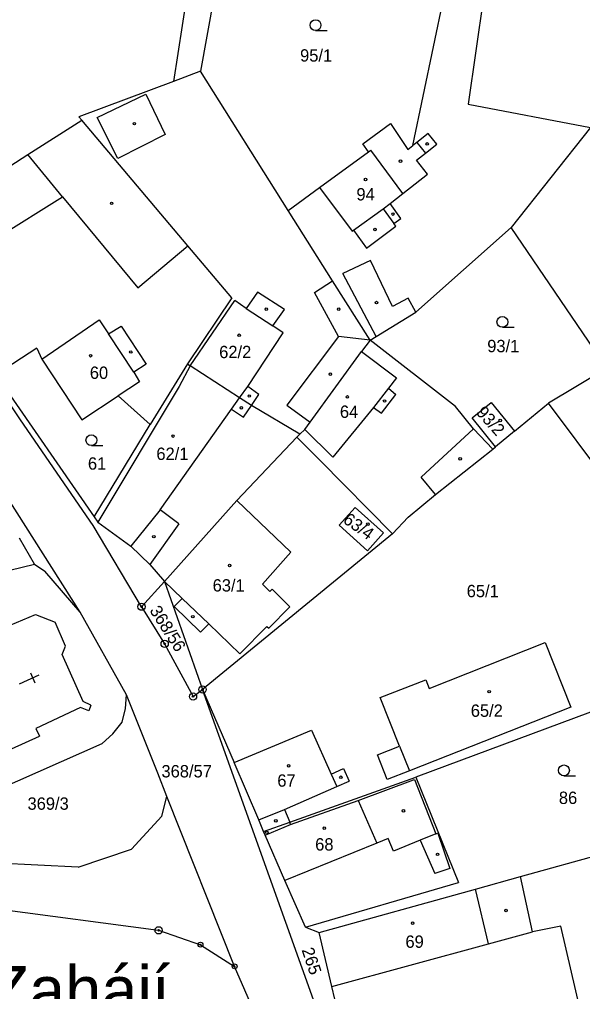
# Model space of a CAD drawing. Extents: x -762263 to -760336, y -1154405 to -1152076.
# Drawn here: x -761616.2 to -761538.5, y -1152485.2 to -1152351.2 of the extents above; entities that cross this region are included whole.
import ezdxf

# ---------------------------------------------------------------- set-up
doc = ezdxf.new("R2010")
doc.units = 0
for name, color, linetype in [('Vrstva 1', 7, 'Continuous'), ('Vrstva 15', 7, 'Continuous'), ('Vrstva 18', 7, 'Continuous'), ('Vrstva 19', 7, 'Continuous'), ('Vrstva 24', 7, 'Continuous'), ('Vrstva 25', 7, 'Continuous'), ('Vrstva 4', 7, 'Continuous'), ('Vrstva 6', 7, 'Continuous')]:
    doc.layers.add(name, color=color, linetype=linetype)

msp = doc.modelspace()

# ---------------------------------------------------------------- linework, layer by layer
at = {"layer": 'Vrstva 1'}
for p, q in [((-761591.52, -1152337.7), (-761594.93, -1152359.73)), ((-761587.54, -1152338.16), (-761591.19, -1152358.32)), ((-761561.91, -1152368.56), (-761556.79, -1152344.07)), ((-761551.73, -1152345.04), (-761554.27, -1152362.87)), ((-761591.19, -1152358.32), (-761594.93, -1152359.73)), ((-761579.11, -1152377.49), (-761591.19, -1152358.32)), ((-761594.93, -1152359.73), (-761607.95, -1152364.61)), ((-761554.27, -1152362.87), (-761537.42, -1152366.06)), ((-761607.56, -1152365.07), (-761607.95, -1152364.61)), ((-761614.98, -1152369.8), (-761607.56, -1152365.07)), ((-761592.94, -1152382.37), (-761607.56, -1152365.07)), ((-761568.82, -1152368.31), (-761564.97, -1152365.51)), ((-761564.97, -1152365.51), (-761562.58, -1152369.09)), ((-761537.42, -1152366.06), (-761548.34, -1152379.84)), ((-761568.01, -1152369.43), (-761568.82, -1152368.31)), ((-761562.58, -1152369.09), (-761561.91, -1152368.56)), ((-761631.67, -1152380.45), (-761614.98, -1152369.8)), ((-761574.76, -1152374.33), (-761568.01, -1152369.43)), ((-761579.11, -1152377.49), (-761574.76, -1152374.33)), ((-761572.97, -1152387.22), (-761579.11, -1152377.49)), ((-761548.34, -1152379.84), (-761561.5, -1152391.51)), ((-761535.14, -1152399.26), (-761548.34, -1152379.84)), ((-761586.87, -1152389.55), (-761592.94, -1152382.37)), ((-761567.81, -1152395.4), (-761572.97, -1152387.22)), ((-761586.87, -1152389.55), (-761593, -1152398.65)), ((-761566.95, -1152394.87), (-761561.5, -1152391.51)), ((-761567.81, -1152395.4), (-761568.99, -1152396.96)), ((-761567.81, -1152395.4), (-761566.95, -1152394.87)), ((-761556.02, -1152404.53), (-761567.81, -1152395.4)), ((-761613.77, -1152396.47), (-761619.46, -1152400.17)), ((-761613.77, -1152396.47), (-761613.05, -1152398)), ((-761613.05, -1152398), (-761607.54, -1152406.37)), ((-761576.08, -1152406.68), (-761568.99, -1152396.96)), ((-761593, -1152398.65), (-761598.11, -1152407.02)), ((-761593, -1152398.65), (-761592.62, -1152398.92)), ((-761585.79, -1152403.34), (-761592.62, -1152398.92)), ((-761535.14, -1152399.26), (-761543.2, -1152404.05)), ((-761619.46, -1152400.17), (-761605.87, -1152419.74)), ((-761607.54, -1152406.37), (-761602.53, -1152403.05)), ((-761598.11, -1152407.02), (-761602.53, -1152403.05)), ((-761584.17, -1152404.39), (-761585.79, -1152403.34)), ((-761577.49, -1152408.36), (-761584.17, -1152404.39)), ((-761553.55, -1152407.58), (-761556.02, -1152404.53)), ((-761553.72, -1152406.08), (-761551.09, -1152403.96)), ((-761551.09, -1152403.96), (-761547.88, -1152407.93)), ((-761547.88, -1152407.93), (-761543.2, -1152404.05)), ((-761527.68, -1152424.89), (-761543.2, -1152404.05)), ((-761550.48, -1152410.09), (-761553.72, -1152406.08)), ((-761605.87, -1152419.74), (-761598.11, -1152407.02)), ((-761576.82, -1152407.69), (-761576.08, -1152406.68)), ((-761550.86, -1152410.4), (-761553.55, -1152407.58)), ((-761586.17, -1152417.49), (-761577.9, -1152408.76)), ((-761577.9, -1152408.76), (-761577.49, -1152408.36)), ((-761577.9, -1152408.76), (-761574.67, -1152411.99)), ((-761577.49, -1152408.36), (-761576.82, -1152407.69)), ((-761547.88, -1152407.93), (-761550.48, -1152410.09)), ((-761550.86, -1152410.4), (-761550.48, -1152410.09)), ((-761558.76, -1152416.64), (-761550.86, -1152410.4)), ((-761574.67, -1152411.99), (-761564.72, -1152422.09)), ((-761562.56, -1152419.78), (-761558.76, -1152416.64)), ((-761586.17, -1152417.49), (-761596.16, -1152428.66)), ((-761569.86, -1152418.45), (-761572.05, -1152420.9)), ((-761565.96, -1152421.95), (-761569.86, -1152418.45)), ((-761605.87, -1152419.74), (-761605.33, -1152420.47)), ((-761605.33, -1152420.47), (-761600.78, -1152423.76)), ((-761572.05, -1152420.9), (-761568.15, -1152424.4)), ((-761562.56, -1152419.78), (-761564.72, -1152422.09)), ((-761564.72, -1152422.09), (-761590.9, -1152443.54)), ((-761568.15, -1152424.4), (-761565.96, -1152421.95)), ((-761614.1, -1152426.24), (-761616.17, -1152422.68)), ((-761600.78, -1152423.76), (-761598.18, -1152426.29)), ((-761619.97, -1152427.66), (-761614.1, -1152426.24)), ((-761614.1, -1152426.24), (-761612.66, -1152427.22)), ((-761598.18, -1152426.29), (-761596.16, -1152428.66)), ((-761607.8, -1152432.87), (-761612.66, -1152427.22)), ((-761596.16, -1152428.66), (-761599.32, -1152432.12)), ((-761596.16, -1152428.66), (-761590.9, -1152443.54)), ((-761601.4, -1152444.25), (-761607.8, -1152432.87)), ((-761599.32, -1152432.12), (-761596.13, -1152437.23)), ((-761620.12, -1152435.81), (-761613.95, -1152433.18)), ((-761613.95, -1152433.18), (-761611.25, -1152434.24)), ((-761609.82, -1152437.56), (-761611.25, -1152434.24)), ((-761559.63, -1152443.38), (-761543.64, -1152437.07)), ((-761543.64, -1152437.07), (-761540.12, -1152445.99)), ((-761610.28, -1152438.71), (-761609.82, -1152437.56)), ((-761596.13, -1152437.23), (-761592.22, -1152444.51)), ((-761607.38, -1152445.2), (-761610.28, -1152438.71)), ((-761566.39, -1152444.65), (-761560.11, -1152442.18)), ((-761560.11, -1152442.18), (-761559.63, -1152443.38)), ((-761592.22, -1152444.51), (-761590.9, -1152443.54)), ((-761571.15, -1152498.75), (-761590.9, -1152443.54)), ((-761590.9, -1152443.54), (-761586.53, -1152453.6)), ((-761601.52, -1152446.15), (-761601.4, -1152444.25)), ((-761597.09, -1152455.08), (-761601.4, -1152444.25)), ((-761563.76, -1152451.33), (-761566.39, -1152444.65)), ((-761530.48, -1152444.07), (-761561.5, -1152455.64)), ((-761607.75, -1152446.02), (-761613.9, -1152448.89)), ((-761606.61, -1152446.46), (-761607.75, -1152446.02)), ((-761606.31, -1152445.7), (-761607.38, -1152445.2)), ((-761606.31, -1152445.7), (-761606.61, -1152446.46)), ((-761602.01, -1152448.03), (-761601.52, -1152446.15)), ((-761540.12, -1152445.99), (-761562.38, -1152454.76)), ((-761613.9, -1152448.89), (-761613.41, -1152449.97)), ((-761603.27, -1152449.66), (-761602.01, -1152448.03)), ((-761586.53, -1152453.6), (-761575.86, -1152449.13)), ((-761575.86, -1152449.13), (-761573.18, -1152455.19)), ((-761626.41, -1152455.8), (-761613.41, -1152449.97)), ((-761604.75, -1152450.96), (-761603.27, -1152449.66)), ((-761624.56, -1152459.76), (-761604.75, -1152450.96)), ((-761566.79, -1152452.52), (-761563.76, -1152451.33)), ((-761565.43, -1152455.96), (-761566.79, -1152452.52)), ((-761583.13, -1152461.51), (-761586.53, -1152453.6)), ((-761573.18, -1152455.19), (-761571.47, -1152454.41)), ((-761571.47, -1152454.41), (-761570.67, -1152456.17)), ((-761595.81, -1152458.29), (-761597.09, -1152455.08)), ((-761578.89, -1152461.84), (-761561.5, -1152455.64)), ((-761562.38, -1152454.76), (-761565.43, -1152455.96)), ((-761561.5, -1152455.64), (-761555.6, -1152470.13)), ((-761579.59, -1152460.08), (-761572.38, -1152456.92)), ((-761572.38, -1152456.92), (-761570.67, -1152456.17)), ((-761586.48, -1152481.7), (-761595.81, -1152458.29)), ((-761579.59, -1152460.08), (-761578.89, -1152461.84)), ((-761582.49, -1152463.13), (-761583.13, -1152461.51)), ((-761582.49, -1152463.13), (-761578.89, -1152461.84)), ((-761547.04, -1152469.31), (-761521.92, -1152462.31)), ((-761582.29, -1152463.6), (-761582.49, -1152463.13)), ((-761579.54, -1152469.86), (-761582.29, -1152463.6)), ((-761576.7, -1152476.31), (-761579.54, -1152469.86)), ((-761576.7, -1152476.31), (-761555.6, -1152470.13)), ((-761553.28, -1152471.04), (-761547.04, -1152469.31)), ((-761545.42, -1152476.96), (-761547.04, -1152469.31)), ((-761574.82, -1152477.02), (-761553.28, -1152471.04)), ((-761630.95, -1152472.2), (-761596.96, -1152476.73)), ((-761596.96, -1152476.73), (-761591.19, -1152478.71)), ((-761576.7, -1152476.31), (-761574.82, -1152477.02)), ((-761573.06, -1152484.47), (-761574.82, -1152477.02)), ((-761551.49, -1152478.61), (-761545.42, -1152476.96)), ((-761541.49, -1152476.16), (-761545.42, -1152476.96)), ((-761538.58, -1152488.6), (-761541.49, -1152476.16)), ((-761573.06, -1152484.47), (-761551.49, -1152478.61)), ((-761591.19, -1152478.71), (-761586.48, -1152481.7)), ((-761572.43, -1152514.02), (-761586.48, -1152481.7)), ((-761572.23, -1152487.97), (-761573.06, -1152484.47))]:
    msp.add_line(p, q, dxfattribs=at)
at = {"layer": 'Vrstva 24'}
for centre, radius in [((-761599.32, -1152432.12), 0.5), ((-761599.32, -1152432.12), 0.1), ((-761596.13, -1152437.23), 0.5), ((-761596.13, -1152437.23), 0.1), ((-761590.9, -1152443.54), 0.5), ((-761590.9, -1152443.54), 0.1), ((-761592.22, -1152444.51), 0.5), ((-761592.22, -1152444.51), 0.1), ((-761596.96, -1152476.73), 0.5), ((-761596.96, -1152476.73), 0.1), ((-761591.19, -1152478.71), 0.335), ((-761591.19, -1152478.71), 0.067), ((-761586.48, -1152481.7), 0.335), ((-761586.48, -1152481.7), 0.067)]:
    msp.add_circle(centre, radius, dxfattribs=at)
at = {"layer": 'Vrstva 25'}
for p, q in [((-761575.32, -1152352.71), (-761573.72, -1152352.71)), ((-761549.55, -1152393.61), (-761547.95, -1152393.61)), ((-761606.24, -1152409.92), (-761604.64, -1152409.92)), ((-761616.15, -1152442.77), (-761613.424, -1152441.518)), ((-761614.646, -1152441.254), (-761614.02, -1152442.617)), ((-761541.07, -1152455.43), (-761539.47, -1152455.43))]:
    msp.add_line(p, q, dxfattribs=at)
for centre, radius in [((-761575.32, -1152351.96), 0.75), ((-761600.31, -1152365.53), 0.175), ((-761559.92, -1152368.33), 0.175), ((-761563.6, -1152370.71), 0.175), ((-761568.42, -1152373.23), 0.175), ((-761603.44, -1152376.52), 0.175), ((-761564.64, -1152378), 0.175), ((-761567.13, -1152380.12), 0.175), ((-761566.92, -1152390.2), 0.175), ((-761582.11, -1152391.11), 0.175), ((-761572.13, -1152391.11), 0.175), ((-761549.55, -1152392.86), 0.75), ((-761585.85, -1152394.7), 0.175), ((-761600.81, -1152397.01), 0.175), ((-761606.34, -1152397.53), 0.175), ((-761573.28, -1152400.06), 0.175), ((-761584.46, -1152403.08), 0.175), ((-761570.93, -1152403.2), 0.175), ((-761565.8, -1152403.77), 0.175), ((-761585.55, -1152404.71), 0.175), ((-761549.85, -1152406.45), 0.175), ((-761606.24, -1152409.17), 0.75), ((-761594.98, -1152408.6), 0.175), ((-761555.37, -1152411.74), 0.175), ((-761568.1, -1152420.75), 0.175), ((-761597.63, -1152422.46), 0.175), ((-761587.17, -1152426.44), 0.175), ((-761592.25, -1152433.5), 0.175), ((-761551.37, -1152443.84), 0.175), ((-761579.03, -1152454.05), 0.175), ((-761541.07, -1152454.68), 0.75), ((-761571.82, -1152455.63), 0.175), ((-761563.2, -1152460.25), 0.175), ((-761580.8, -1152461.64), 0.175), ((-761574.11, -1152462.64), 0.175), ((-761582.04, -1152463.23), 0.175), ((-761558.49, -1152466.25), 0.175), ((-761549.05, -1152473.99), 0.175), ((-761561.93, -1152475.74), 0.175)]:
    msp.add_circle(centre, radius, dxfattribs=at)
at = {"layer": 'Vrstva 4'}
for p, q in [((-761616.01, -1152406.38), (-761652.68, -1152351.91)), ((-761605.46, -1152364.7), (-761598.75, -1152361.45)), ((-761598.75, -1152361.45), (-761596.05, -1152367.03)), ((-761602.6, -1152370.35), (-761605.46, -1152364.7)), ((-761596.05, -1152367.03), (-761602.6, -1152370.35)), ((-761559.78, -1152366.88), (-761561.35, -1152368.12)), ((-761558.6, -1152368.38), (-761559.78, -1152366.88)), ((-761561.35, -1152368.12), (-761561.91, -1152368.56)), ((-761561.35, -1152368.12), (-761560.18, -1152369.62)), ((-761560.18, -1152369.62), (-761558.6, -1152368.38)), ((-761610.24, -1152375.63), (-761614.98, -1152369.8)), ((-761568.01, -1152369.43), (-761567.68, -1152369.19)), ((-761563.29, -1152375.17), (-761567.68, -1152369.19)), ((-761561.41, -1152370.58), (-761560.18, -1152369.62)), ((-761559.9, -1152372.51), (-761561.41, -1152370.58)), ((-761563.29, -1152375.17), (-761559.9, -1152372.51)), ((-761574.76, -1152374.33), (-761570.26, -1152380.35)), ((-761565.04, -1152376.55), (-761563.29, -1152375.17)), ((-761627.92, -1152386.68), (-761610.24, -1152375.63)), ((-761610.24, -1152375.63), (-761599.81, -1152388.18)), ((-761565.98, -1152377.28), (-761565.04, -1152376.55)), ((-761563.55, -1152378.62), (-761565.04, -1152376.55)), ((-761570.1, -1152380.23), (-761565.98, -1152377.28)), ((-761565.98, -1152377.28), (-761564.53, -1152379.31)), ((-761564.53, -1152379.31), (-761563.55, -1152378.62)), ((-761564.27, -1152379.68), (-761564.53, -1152379.31)), ((-761570.26, -1152380.35), (-761570.1, -1152380.23)), ((-761570.1, -1152380.23), (-761568.29, -1152382.68)), ((-761568.29, -1152382.68), (-761564.27, -1152379.68)), ((-761599.81, -1152388.18), (-761592.94, -1152382.37)), ((-761567.76, -1152384.39), (-761571.54, -1152386.19)), ((-761564.71, -1152390.76), (-761567.76, -1152384.39)), ((-761566.95, -1152394.87), (-761571.54, -1152386.19)), ((-761575.48, -1152388.8), (-761572.97, -1152387.22)), ((-761583.32, -1152388.76), (-761584.88, -1152391)), ((-761579.61, -1152391.13), (-761583.32, -1152388.76)), ((-761572.16, -1152394.88), (-761575.48, -1152388.8)), ((-761592.62, -1152398.92), (-761586.47, -1152389.91)), ((-761584.88, -1152391), (-761586.47, -1152389.91)), ((-761562.56, -1152389.58), (-761564.71, -1152390.76)), ((-761561.5, -1152391.51), (-761562.56, -1152389.58)), ((-761584.88, -1152391), (-761581.19, -1152393.42)), ((-761581.19, -1152393.42), (-761579.61, -1152391.13)), ((-761613.05, -1152398), (-761605.18, -1152392.59)), ((-761605.18, -1152392.59), (-761603.87, -1152394.51)), ((-761603.87, -1152394.51), (-761602.11, -1152393.43)), ((-761602.11, -1152393.43), (-761598.67, -1152398.7)), ((-761579.77, -1152394.38), (-761581.19, -1152393.42)), ((-761600.38, -1152399.77), (-761603.87, -1152394.51)), ((-761584.68, -1152401.78), (-761579.77, -1152394.38)), ((-761572.16, -1152394.88), (-761579.29, -1152404.34)), ((-761567.81, -1152395.4), (-761572.16, -1152394.88)), ((-761568.99, -1152396.96), (-761564.14, -1152400.59)), ((-761598.67, -1152398.7), (-761600.38, -1152399.77)), ((-761592.62, -1152398.92), (-761594.15, -1152401.75)), ((-761600.38, -1152399.77), (-761599.61, -1152401.12)), ((-761564.14, -1152400.59), (-761565.26, -1152402)), ((-761594.15, -1152401.75), (-761605.33, -1152420.47)), ((-761599.61, -1152401.12), (-761602.53, -1152403.05)), ((-761585.79, -1152403.34), (-761584.68, -1152401.78)), ((-761583.12, -1152402.86), (-761584.68, -1152401.78)), ((-761565.26, -1152402), (-761567.34, -1152404.64)), ((-761565.26, -1152402), (-761564.23, -1152402.87)), ((-761586.89, -1152404.89), (-761585.79, -1152403.34)), ((-761584.17, -1152404.39), (-761583.12, -1152402.86)), ((-761566.23, -1152405.42), (-761564.23, -1152402.87)), ((-761596.73, -1152418.76), (-761586.89, -1152404.89)), ((-761586.89, -1152404.89), (-761585.28, -1152406)), ((-761585.28, -1152406), (-761584.17, -1152404.39)), ((-761579.29, -1152404.34), (-761576.08, -1152406.68)), ((-761567.34, -1152404.64), (-761572.93, -1152411.53)), ((-761567.34, -1152404.64), (-761566.23, -1152405.42)), ((-761605.98, -1152420.94), (-761616.01, -1152406.38)), ((-761560.74, -1152414.27), (-761553.55, -1152407.58)), ((-761572.93, -1152411.53), (-761576.82, -1152407.69)), ((-761607.8, -1152432.87), (-761621.94, -1152410.62)), ((-761558.76, -1152416.64), (-761560.74, -1152414.27)), ((-761578.72, -1152424.62), (-761586.17, -1152417.49)), ((-761596.73, -1152418.76), (-761600.78, -1152423.76)), ((-761594.16, -1152420.71), (-761596.73, -1152418.76)), ((-761599.32, -1152432.12), (-761605.98, -1152420.94)), ((-761594.16, -1152420.71), (-761598.18, -1152426.29)), ((-761582.63, -1152429.03), (-761578.72, -1152424.62)), ((-761593.72, -1152430.97), (-761596.16, -1152428.66)), ((-761581.61, -1152430.02), (-761582.63, -1152429.03)), ((-761581.3, -1152429.7), (-761581.61, -1152430.02)), ((-761578.87, -1152432.13), (-761581.3, -1152429.7)), ((-761593.72, -1152430.97), (-761594.8, -1152432.07)), ((-761590.06, -1152434.49), (-761593.72, -1152430.97)), ((-761594.8, -1152432.07), (-761591.19, -1152435.63)), ((-761581.78, -1152435.09), (-761578.87, -1152432.13)), ((-761591.19, -1152435.63), (-761590.06, -1152434.49)), ((-761590.06, -1152434.49), (-761585.75, -1152438.63)), ((-761585.75, -1152438.63), (-761582.03, -1152434.84)), ((-761582.03, -1152434.84), (-761581.78, -1152435.09)), ((-761563.76, -1152451.33), (-761562.38, -1152454.76)), ((-761573.18, -1152455.19), (-761572.38, -1152456.92)), ((-761569.45, -1152458.82), (-761561.81, -1152455.97)), ((-761561.81, -1152455.97), (-761561.67, -1152455.92)), ((-761561.67, -1152455.92), (-761558.73, -1152463.44)), ((-761578.76, -1152462.16), (-761569.45, -1152458.82)), ((-761569.45, -1152458.82), (-761566.87, -1152464.72)), ((-761583.13, -1152461.51), (-761579.59, -1152460.08)), ((-761582.29, -1152463.6), (-761578.76, -1152462.16)), ((-761578.76, -1152462.16), (-761578.89, -1152461.84)), ((-761558.73, -1152463.44), (-761560.88, -1152464.32)), ((-761558.73, -1152463.44), (-761558.46, -1152463.33)), ((-761558.46, -1152463.33), (-761556.78, -1152468.19)), ((-761566.87, -1152464.72), (-761579.54, -1152469.86)), ((-761565.3, -1152464.08), (-761566.87, -1152464.72)), ((-761564.58, -1152465.83), (-761565.3, -1152464.08)), ((-761560.88, -1152464.32), (-761564.58, -1152465.83)), ((-761560.88, -1152464.32), (-761558.86, -1152468.91)), ((-761556.78, -1152468.19), (-761558.86, -1152468.91)), ((-761551.49, -1152478.61), (-761553.28, -1152471.04))]:
    msp.add_line(p, q, dxfattribs=at)
at = {"layer": 'Vrstva 6'}
for p, q in [((-761596.52, -1152461), (-761595.81, -1152458.29)), ((-761600.71, -1152465.54), (-761596.52, -1152461)), ((-761608.07, -1152468.02), (-761600.71, -1152465.54)), ((-761608.07, -1152468.02), (-761620.8, -1152467.4))]:
    msp.add_line(p, q, dxfattribs=at)

# ---------------------------------------------------------------- texts
at = {"layer": 'Vrstva 15'}
msp.add_text('Zahájí', height=6.7, dxfattribs=at).set_placement((-761620.305, -1152488.33))
at = {"layer": 'Vrstva 18'}
for s, p in [('95/1', (-761577.453, -1152356.98)), ('93/1', (-761551.643, -1152397.04)), ('61', (-761606.713, -1152413.23)), ('65/1', (-761554.473, -1152430.81)), ('368/57', (-761596.573, -1152455.65)), ('369/3', (-761615.047, -1152460.11)), ('86', (-761541.763, -1152459.31))]:
    msp.add_text(s, height=1.7, dxfattribs=at).set_placement(p)
for s, rotation, p in [('368/56', 302.40713, (-761598.273, -1152432.64)), ('265', 288.65614, (-761577.264, -1152479.424))]:
    msp.add_text(s, height=1.7, rotation=rotation, dxfattribs=at).set_placement(p)
at = {"layer": 'Vrstva 19'}
for s, p in [('94', (-761569.683, -1152376.12)), ('62/2', (-761588.613, -1152397.86)), ('60', (-761606.453, -1152400.72)), ('64', (-761571.963, -1152406.09)), ('62/1', (-761597.273, -1152411.89)), ('63/1', (-761589.513, -1152430.03)), ('65/2', (-761553.913, -1152447.3)), ('67', (-761580.595, -1152456.93)), ('68', (-761575.373, -1152465.73)), ('69', (-761562.923, -1152479.14))]:
    msp.add_text(s, height=1.7, dxfattribs=at).set_placement(p)
for s, rotation, p in [('93/2', 311.68904, (-761553.282, -1152405.411)), ('63/4', 324.58059, (-761571.657, -1152420.439))]:
    msp.add_text(s, height=1.7, rotation=rotation, dxfattribs=at).set_placement(p)

doc.saveas('drawing.dxf')
